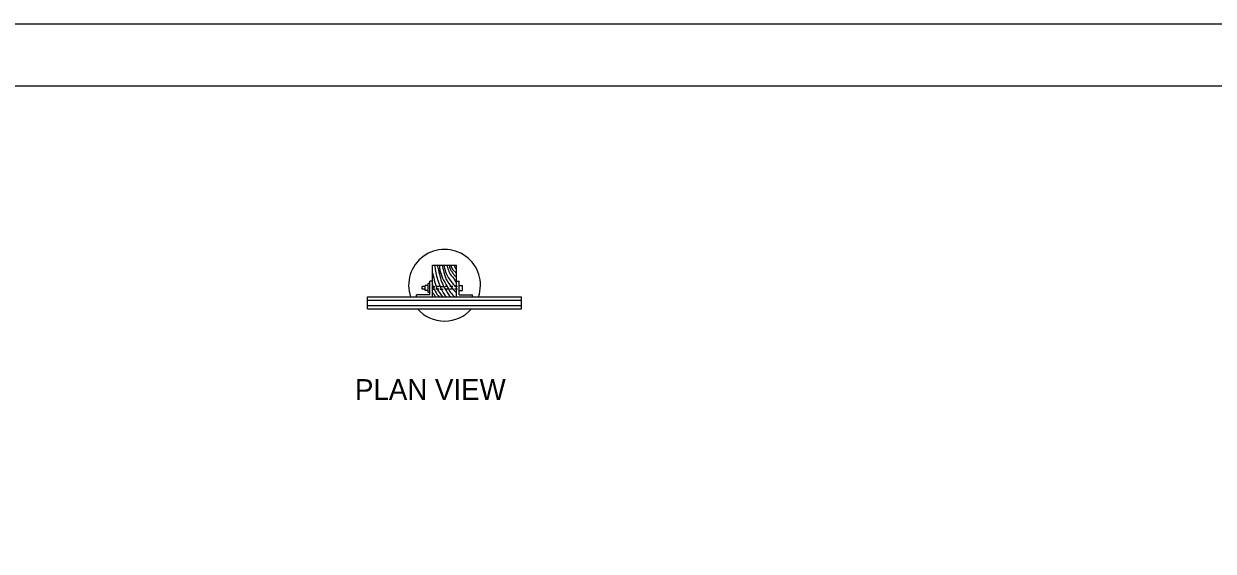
# Model space of a CAD drawing. Extents: x -1958 to 628, y -879 to 309.
# Drawn here: x -1670.2 to -1382.9, y 182 to 309.4 of the extents above; entities that cross this region are included whole.
import ezdxf

# ---------------------------------------------------------------- set-up
doc = ezdxf.new("R2010")
doc.units = 0
for name, color, linetype in [('1', 7, 'Continuous'), ('2', 7, 'Continuous'), ('3', 7, 'Continuous'), ('PLT-BNDY', 7, 'Continuous')]:
    doc.layers.add(name, color=color, linetype=linetype)

msp = doc.modelspace()

# ---------------------------------------------------------------- linework, layer by layer
at = {"layer": '1'}
msp.add_line((-1918.39, 294.44), (-1132.39, 294.44), dxfattribs=at)
at = {"layer": '2'}
for p, q in [((-1571.45, 251.07), (-1565.65, 251.07)), ((-1571.45, 247.2), (-1572.15, 247.2)), ((-1565.65, 247.2), (-1565.03, 247.2)), ((-1572.15, 246.66), (-1572.53, 246.66)), ((-1572.15, 244.5), (-1572.53, 244.5)), ((-1587.17, 243.43), (-1559.93, 243.43)), ((-1587.17, 243.43), (-1559.93, 243.43)), ((-1587.17, 242.65), (-1550, 242.65)), ((-1572.15, 243.95), (-1575.32, 243.95)), ((-1565.03, 243.95), (-1561.78, 243.95)), ((-1559.93, 243.43), (-1550, 243.43)), ((-1559.93, 243.43), (-1550, 243.43)), ((-1587.17, 241.33), (-1550, 241.33)), ((-1587.17, 240.55), (-1550, 240.55))]:
    msp.add_line(p, q, dxfattribs=at)
at = {"layer": '3'}
for p, q in [((-1571.45, 243.43), (-1571.45, 251.07)), ((-1565.65, 243.43), (-1565.65, 251.07)), ((-1572.15, 243.95), (-1572.15, 247.2)), ((-1565.03, 243.95), (-1565.03, 247.2)), ((-1574, 245.27), (-1574, 245.97)), ((-1573.23, 245.97), (-1574, 245.97)), ((-1573.23, 245.27), (-1574, 245.27)), ((-1573.23, 244.96), (-1573.23, 246.2)), ((-1572.53, 246.2), (-1573.23, 246.2)), ((-1572.53, 244.96), (-1573.23, 244.96)), ((-1572.53, 244.5), (-1572.53, 246.66)), ((-1571.68, 245.97), (-1570.91, 245.97)), ((-1571.68, 245.27), (-1570.91, 245.27)), ((-1569.9, 245.97), (-1570.68, 245.97)), ((-1569.9, 245.27), (-1570.68, 245.27)), ((-1569.59, 245.97), (-1568.9, 245.97)), ((-1569.59, 245.27), (-1568.9, 245.27)), ((-1567.74, 245.97), (-1568.43, 245.97)), ((-1567.74, 245.27), (-1568.43, 245.27)), ((-1566.58, 245.97), (-1567.27, 245.97)), ((-1566.58, 245.27), (-1567.27, 245.27)), ((-1565.42, 245.97), (-1566.19, 245.97)), ((-1565.42, 245.27), (-1566.19, 245.27)), ((-1565.03, 246.2), (-1564.26, 246.2)), ((-1565.03, 244.96), (-1564.26, 244.96)), ((-1564.26, 244.96), (-1564.26, 246.2)), ((-1587.17, 240.55), (-1587.17, 243.43)), ((-1575.32, 243.43), (-1575.32, 243.95)), ((-1561.78, 243.43), (-1561.78, 243.95)), ((-1550, 240.55), (-1550, 243.43))]:
    msp.add_line(p, q, dxfattribs=at)
for start, end in [(341.1525, 198.8475), (220.9893, 319.0107)]:
    msp.add_arc((-1568.57, 246.24), 8.67, start, end, dxfattribs=at)
for points in [[(-1570.99, 251.07), (-1570.75, 249.68), (-1570.37, 248.05), (-1569.83, 246.35), (-1568.9, 244.42), (-1568.2, 243.43)], [(-1570.37, 251.07), (-1570.06, 249.91), (-1568.9, 246.2), (-1568.05, 244.73), (-1567.43, 243.8), (-1567.13, 243.43)], [(-1569.83, 250.99), (-1569.67, 249.83), (-1569.05, 247.98), (-1567.97, 245.97), (-1567.12, 244.5), (-1566.2, 243.43)], [(-1569.13, 251.07), (-1568.97, 250.37), (-1568.43, 248.36), (-1567.97, 247.28), (-1567.04, 246.04), (-1566.42, 245.11), (-1565.73, 244.57)], [(-1568.74, 250.99), (-1568.43, 249.83), (-1567.89, 248.44), (-1566.96, 247.13), (-1566.34, 246.35), (-1565.73, 245.81)], [(-1567.97, 250.99), (-1567.74, 250.22), (-1567.5, 249.6), (-1567.2, 248.9), (-1566.34, 247.9), (-1565.88, 247.05), (-1565.73, 246.89)], [(-1567.43, 250.99), (-1567.12, 249.99), (-1566.73, 249.45), (-1566.27, 248.75), (-1565.73, 248.21)], [(-1567.04, 250.99), (-1566.73, 250.22), (-1566.34, 249.76), (-1565.73, 249.21)], [(-1566.19, 250.99), (-1566.11, 250.61), (-1566.04, 250.45), (-1565.73, 250.22)], [(-1571.45, 249.21), (-1570.91, 246.89), (-1570.21, 245.04), (-1569.04, 243.43)], [(-1571.45, 246.35), (-1570.83, 244.8), (-1569.9, 243.43)], [(-1571.45, 244.5), (-1570.99, 243.8), (-1570.73, 243.43)]]:
    msp.add_spline(points, degree=3, dxfattribs=at)
at = {"layer": 'PLT-BNDY'}
msp.add_lwpolyline([(-1958.39, 309.44), (-1117.39, 309.44), (-1117.39, -284.56), (-1958.39, -284.56)], close=True, dxfattribs=at)

# ---------------------------------------------------------------- texts
at = {"layer": '3'}
msp.add_text('PLAN VIEW', height=5, dxfattribs=at).set_placement((-1590.21, 218.55))

doc.saveas('drawing.dxf')
